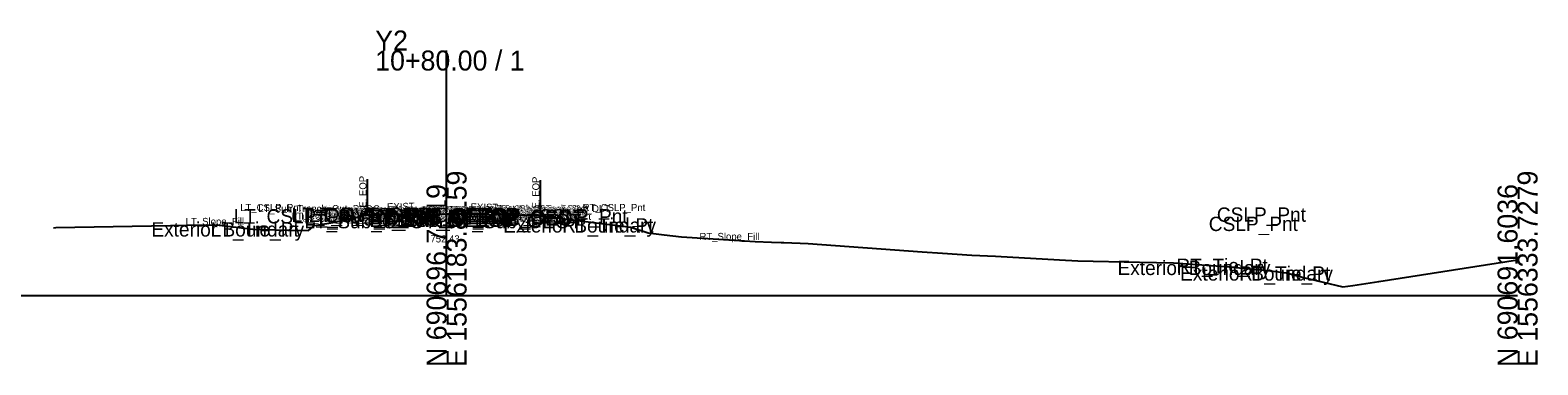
# Model space of a CAD drawing. Extents: x -26 to 303, y -10 to 5027.
# Drawn here: x 91.7 to 302.8, y -9.7 to 37.1 of the extents above; entities that cross this region are included whole.
import ezdxf

# ---------------------------------------------------------------- set-up
doc = ezdxf.new("R2010")
doc.units = 0
for name, color, linetype in [('Default', 7, 'Continuous'), ('Exist Cross Section Cell', 7, 'Continuous'), ('Exist XS Center Line Elevation Label', 7, 'Continuous'), ('Exist XS Ground Line', 7, 'Continuous'), ('Prop XS Label Text', 7, 'Continuous'), ('Prop XSC Text', 7, 'Continuous'), ('Scratch_Level_0', 7, 'Continuous')]:
    doc.layers.add(name, color=color, linetype=linetype)

msp = doc.modelspace()

# ---------------------------------------------------------------- linework, layer by layer
at = {"layer": 'Exist Cross Section Cell'}
for p, q in [((150, 0), (150, 34.29)), ((0, 0), (150, 0)), ((150, 0), (300, 0))]:
    msp.add_line(p, q, dxfattribs=at)
at = {"layer": 'Exist XS Ground Line'}
msp.add_lwpolyline([(94.96, 9.5), (95.26, 9.51), (111.32, 9.8), (113.75, 9.87), (117.79, 9.92), (122.86, 9.31), (127.75, 9.14), (130.68, 9.12), (131.48, 9.8), (134.65, 10.34), (138.88, 11.28), (140.06, 11.35), (141.97, 11.37), (150, 11.43), (151.01, 11.43), (160.72, 11.27), (161.28, 11.26), (163.1, 11.17), (164.59, 10.98), (175.8, 9.57), (178.23, 8.8), (180.45, 8.48), (182.88, 8.21), (193.23, 7.58), (195.51, 7.49), (196.87, 7.44), (197.24, 7.41), (200.64, 7.28), (216.63, 6.1), (219.47, 5.91), (223.55, 5.65), (226.89, 5.51), (235.83, 5.01), (238.41, 4.88), (247.07, 4.68), (251.79, 4.56), (259.07, 4.05), (265.03, 3.51), (267.65, 3.2), (270, 2.52), (275.53, 1.2), (276.92, 1.39), (280.57, 1.98), (300, 5)], dxfattribs=at)
at = {"layer": 'Prop XS Label Text'}
for p, q in [((138.88, 16.28), (138.88, 11.28)), ((163.1, 16.17), (163.1, 11.17))]:
    msp.add_line(p, q, dxfattribs=at)

# ---------------------------------------------------------------- texts
at = {"layer": 'Default'}
for s, p in [('LT_CSLP_Pnt', (120.17, 10.09)), ('LT_CG_Top_BOC', (128.28, 10.29)), ('LT_Sub_OEOT', (130.08, 9.41)), ('LT_PV2_OEOT', (130.17, 10.04)), ('LT_PV3_OEOT', (130.17, 9.79)), ('LT_PV1_OEOT', (130.74, 10.29)), ('RT_Sub_OEEOP', (139.17, 9.61)), ('LT_Sub_OEEOP', (139.21, 9.61)), ('RT_PV2_OEEOP', (139.26, 10.24)), ('RT_PV3_OEEOP', (139.26, 9.99)), ('LT_PV2_OEEOP', (139.31, 10.24)), ('LT_PV3_OEEOP', (139.31, 9.99)), ('RT_PV1_OEEOP', (139.83, 10.36)), ('LT_PV1_OEEOP', (139.87, 10.36)), ('RT_PV2_IEEOP', (139.91, 10.24)), ('LT_PV2_IEEOP', (139.95, 10.24)), ('RT_PV1_IEEOP', (140.47, 10.36)), ('LT_PV1_IEEOP', (140.52, 10.36)), ('RT_PV2_PGL', (141.17, 10.24)), ('LT_PV2_PGL', (141.21, 10.24)), ('RT_PV1_PGL', (141.73, 10.49)), ('LT_PV1_PGL', (141.78, 10.49)), ('RT_Sub_OEOT', (150.03, 9.41)), ('RT_PV2_OEOT', (150.13, 10.04)), ('RT_PV3_OEOT', (150.13, 9.79)), ('RT_PV1_OEOT', (150.69, 10.29)), ('Exterior Boundary', (157.93, 8.82)), ('CSLP_Pnt', (162.87, 10.09)), ('RT_Tie_Pt', (166.18, 8.82)), ('CSLP_Pnt', (256.75, 9.03)), ('CSLP_Pnt', (257.88, 10.33)), ('Exterior Boundary', (108.65, 8.26)), ('LT_Tie_Pt', (116.95, 8.26)), ('Exterior Boundary', (243.97, 2.87)), ('RT_Tie_Pt', (252.22, 3.17)), ('Exterior Boundary', (252.73, 2.09)), ('RT_Tie_Pt', (260.98, 2.09))]:
    msp.add_text(s, height=2, dxfattribs=at).set_placement(p)
at = {"layer": 'Exist Cross Section Cell'}
for s, p in [('Y2', (140, 34.29)), ('10+80.00 / 1', (140, 31.49))]:
    msp.add_text(s, height=2.8, dxfattribs=at).set_placement(p)
for s, p in [('E 1556183.8159', (152.8, -10)), ('E 1556333.7279', (302.8, -10)), ('N 690696.7419', (150, -10)), ('N 690691.6036', (300, -10))]:
    msp.add_text(s, height=2.8, rotation=90, dxfattribs=at).set_placement(p)
at = {"layer": 'Exist XS Center Line Elevation Label'}
msp.add_text('752.43', height=1, dxfattribs=at).set_placement((147.74, 7.43))
at = {"layer": 'Prop XS Label Text'}
for p in [(138.78, 12.29), (163, 12.19)]:
    msp.add_text('E. EOP', height=1, rotation=90, dxfattribs=at).set_placement(p)
at = {"layer": 'Prop XSC Text'}
for rotation, p in [(1.1458, (141.67, 11.92)), (358.8542, (153.36, 11.91))]:
    msp.add_text('EXIST.', height=1, rotation=rotation, dxfattribs=at).set_placement(p)
at = {"layer": 'Scratch_Level_0'}
for s, p in [('LT_CSLP_Pnt', (121.09, 11.82)), ('LT_Sub_Trench_Out_DLT', (123.62, 11.67)), ('RT_Sub_Trench_Out_DLT', (156.92, 11.67)), ('RT_CSLP_Pnt', (169.06, 11.82)), ('LT_Slope_Fill', (113.46, 9.87)), ('LT_CG1_Shelf_Out', (128.28, 10.6)), ('LT_CG_Top_Face', (129.63, 11.63)), ('LT_CG_Top_BOC', (129.64, 11.63)), ('LT_CG_Bot_BOC', (129.66, 10.61)), ('LT_Sub_OEOP', (129.76, 10.31)), ('LT_CG_Top_Gut', (130.12, 11.13)), ('LT_PV_Sub_Tie_Out', (132.49, 11.35)), ('LT_CG_Bot_IE', (132.96, 10.66)), ('LT_Sub_OEOT', (133.04, 10.37)), ('LT_PV2_OEOT', (133.09, 11)), ('LT_PV3_OEOT', (133.09, 10.75)), ('LT_PV1_OEOT', (133.37, 11.25)), ('LT_PV_OEEOP_EG', (133.77, 11.35)), ('LT_Sub_OEEOP', (134.61, 10.41)), ('LT_PV2_OEEOP', (134.65, 11.04)), ('LT_PV3_OEEOP', (134.65, 10.79)), ('LT_PV1_OEEOP', (134.94, 11.16)), ('RT_PV_IEEOP_EG', (144.07, 11.43)), ('LT_PV_IEEOP_EG', (144.09, 11.43)), ('RT_PV2_IEEOP', (144.95, 11.24)), ('RT_PV3_IEEOP', (144.95, 10.99)), ('LT_PV2_IEEOP', (144.98, 11.24)), ('LT_PV3_IEEOP', (144.98, 10.99)), ('RT_PV1_IEEOP', (145.24, 11.36)), ('LT_PV1_IEEOP', (145.26, 11.36)), ('PV2_PGL', (146.95, 11.24)), ('PV1_PGL', (147.24, 11.49)), ('RT_PV_Sub_Tie_Out', (152.43, 11.28)), ('RT_PV_OEEOP_EG', (153.75, 11.28)), ('RT_Sub_OEEOP', (154.58, 10.41)), ('RT_PV2_OEEOP', (154.63, 11.04)), ('RT_PV3_OEEOP', (154.63, 10.79)), ('RT_PV1_OEEOP', (154.91, 11.16)), ('RT_CG_Bot_IE', (156.93, 10.66)), ('RT_Sub_OEOT', (157.02, 10.37)), ('RT_PV2_OEOT', (157.06, 11)), ('RT_PV3_OEOT', (157.06, 10.75)), ('RT_PV1_OEOT', (157.35, 11.25)), ('RT_CG_Top_Face', (157.61, 11.63)), ('RT_CG_Top_Gut', (158.09, 11.13)), ('RT_CG1_Shelf_Out', (158.25, 10.6)), ('RT_CG_Top_BOC', (158.62, 11.63)), ('RT_CG_Bot_BOC', (158.63, 10.61)), ('RT_Sub_OEOP', (160.33, 10.31)), ('RT_Slope_Fill', (185.42, 7.77))]:
    msp.add_text(s, height=1, dxfattribs=at).set_placement(p)

doc.saveas('drawing.dxf')
